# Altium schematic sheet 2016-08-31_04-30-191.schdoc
size 331 x 134 mm; SheetNumber: 1; SheetTotal: 1
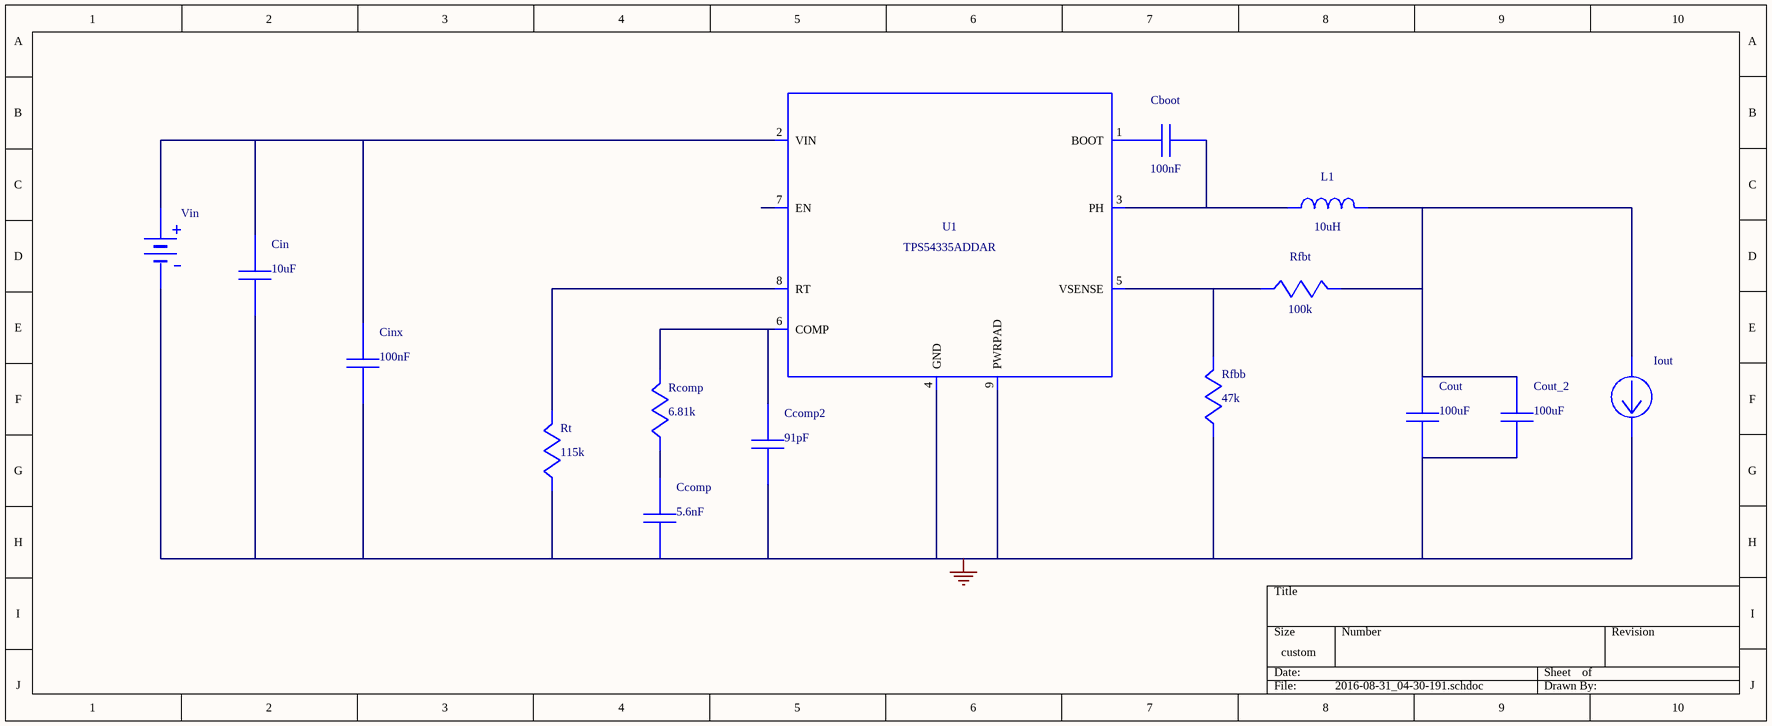
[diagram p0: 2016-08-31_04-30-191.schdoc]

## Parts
Cboot  value 100nF  (hidden comment: C0805C104K5RACTU)
Ccomp  value 5.6nF  (hidden comment: CC0805KRX7R9BB562)
Ccomp2  value 91pF  (hidden comment: CL21C910JBANNNC)
Cin  value 10uF  (hidden comment: GRM31CR71E106KA12L)
Cinx  value 100nF  (hidden comment: C0805C104K5RACTU)
Cout  value 100uF  (hidden comment: GRM31CD80G107ME39L)
Cout_2  value 100uF  (hidden comment: GRM31CD80G107ME39L)
Iout  WB_CURRENT_LOAD  (value not drawn)
L1  value 10uH  (hidden comment: SRU1038-100Y)
Rcomp  value 6.81k  (hidden comment: CRCW04026K81FKED)
Rfbb  value 47k  (hidden comment: RC0603FR-0747KL)
Rfbt  value 100k  (hidden comment: CRCW0402100KFKED)
Rt  value 115k  (hidden comment: CRCW0402115KFKED)
U1  TPS54335ADDAR
Vin  WB_BATTERY  (value not drawn)

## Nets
0: Ccomp.2 Ccomp2.2 Cin.2 Cinx.2 Cout.2 Cout_2.2 Iout.2(-) Rfbb.2 Rt.2 U1.4(GND) U1.9(PWRPAD) Vin.2(-)
NetCboot_1: Cboot.1 U1.1(BOOT)
NetCboot_2: Cboot.2 L1.1 U1.3(PH)
NetCcomp2_1: Ccomp2.1 Rcomp.1 U1.6(COMP)
NetCcomp_1: Ccomp.1 Rcomp.2
NetCin_1: Cin.1 Cinx.1 U1.2(VIN) Vin.1(+)
NetCout_1: Cout.1 Cout_2.1 Iout.1(+) L1.2 Rfbt.1
NetRfbb_1: Rfbb.1 Rfbt.2 U1.5(VSENSE)
NetRt_1: Rt.1 U1.8(RT)

Not connected (* = marked no-connect by the designer): U1 7(EN)

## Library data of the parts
Cboot Cinx = C0805C104K5RACTU: Manufacturer Name: Kemet
Ccomp = CC0805KRX7R9BB562: CC0805KRX7R9BB56; Manufacturer Name: Yageo America
Ccomp2 = CL21C910JBANNNC: Manufacturer Name: Samsung Electro-Mechanics
Cin = GRM31CR71E106KA12L: GRM31CR71E106KA1; Manufacturer Name: MuRata
Cout Cout_2 = GRM31CD80G107ME39L: GRM31CD80G107ME3; Manufacturer Name: MuRata
L1 = SRU1038-100Y: Manufacturer Name: Bourns
Rcomp = CRCW04026K81FKED: Manufacturer Name: Vishay-Dale
Rfbb = RC0603FR-0747KL: Manufacturer Name: Yageo America
Rfbt = CRCW0402100KFKED: Manufacturer Name: Vishay-Dale
Rt = CRCW0402115KFKED: Manufacturer Name: Vishay-Dale
U1 = TPS54335ADDAR: Manufacturer Name: Texas Instruments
